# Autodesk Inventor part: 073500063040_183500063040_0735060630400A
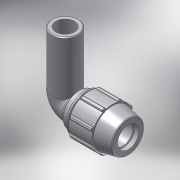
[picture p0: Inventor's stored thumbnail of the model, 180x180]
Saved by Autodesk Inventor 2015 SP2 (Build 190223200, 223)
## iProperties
Created: 2017-02
Part Number: 073500063040_183500063040_0735060630400A
Material: PVC-Piping
Description: PLASSON 90° ELBOW ADAPTOR 63-40
Document SubType Name: Modeling
Designer: KIM
Mass: 92.6774 g
Surface Area: 199.44 cm^2
Volume: 66.1981 cm^3
Density: 1.4 g/cm^3
Appearance: Smooth - White
Author: KIM
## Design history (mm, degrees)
derived "07350.ipt"
feature "Solid1::07350.ipt"
tag "TaggingFeature1"
body "Solid1"
other parameters: "d2" = 63, "d4" = 13.41667, "d5" = 40.25, "d7" = 113, "d11" = 5.36667, "d13" = 120 deg, "d14" = 81.9, "d15" = 12 deg, "d16" = 98.31, "d18" = 3.15, "d19" = 35 deg, "d20" = 17.5 deg, "d21" = 105.09, "d23" = 0, "d25" = 360 deg, "d27" = 2.26, "d33" = 1.26, "d42" = 59.57, "d43" = 3.39, "d46" = 1.89, "d51" = 161, "d68" = 5.36667, "d72" = 106, "d76" = 28, "d79" = 16, "d80" = 1.2, "d91" = 84.75, "d95" = 28, "d96" = 13.41667, "d97" = 50 deg, "d98" = 63.6, "d99" = 0, "d100" = 0, "d_" = 63, "E_" = 113, "A_" = 161, "A_1" = 106
